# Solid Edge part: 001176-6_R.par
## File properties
Last saved by: morva
Revision: 82
Accuracy: 0.990
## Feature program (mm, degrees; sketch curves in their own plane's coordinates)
body "unnamed Body 1"
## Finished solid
Body 1: solid body, 10 faces, 24 edges, 12 vertices.
  Faces by surface: torus 8, spline 2
  Edges by curve: circle 18, curve on surface 4, spline 2
Bounding box of the edges (mm; curved faces can reach further): 5.500 x 5.500 x 8.500, from (-2.75, -2.75, -0.25) to (2.75, 2.75, 8.25).
Toroidal faces (ring radius, tube radius in mm): R2.5 r0.25 x8
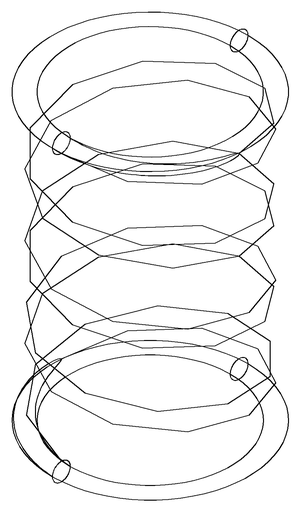
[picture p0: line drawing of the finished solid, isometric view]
